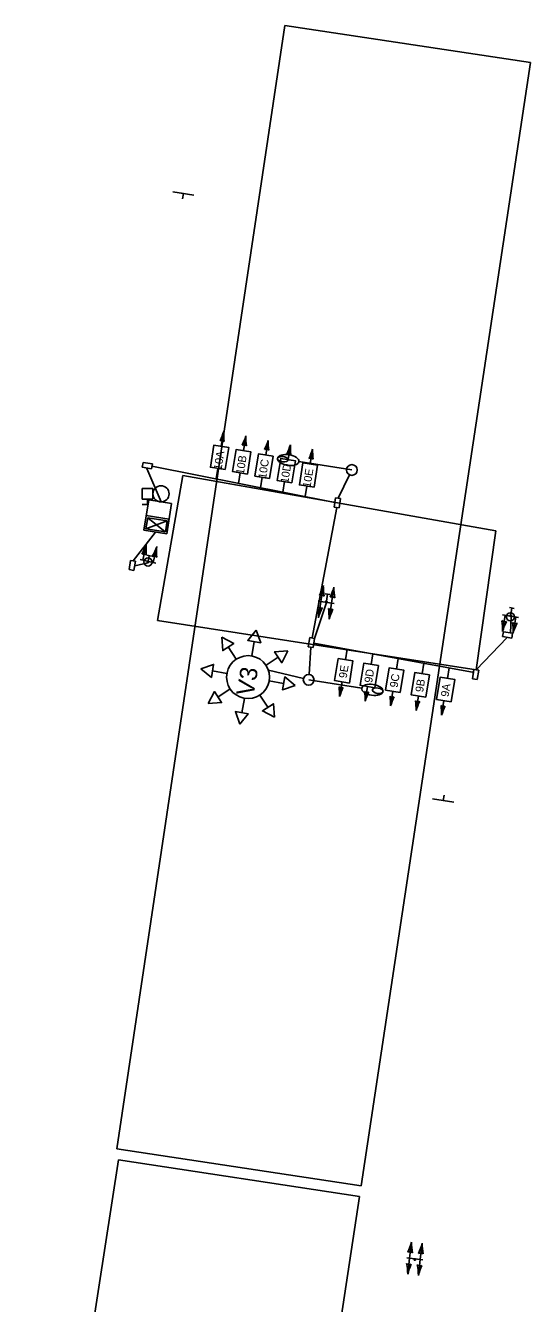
# Model space of a CAD drawing. Extents: x 991933 to 997296, y 1973751 to 1976728.
# Drawn here: x 992033.2 to 992127.2, y 1975751.3 to 1975989 of the extents above; entities that cross this region are included whole.
import ezdxf

# ---------------------------------------------------------------- set-up
doc = ezdxf.new("R2010")
doc.units = 0
for name, color, linetype in [('S_CROSS_DRAIN', 7, 'Continuous'), ('S_CURB', 7, 'Continuous'), ('S_DRIVEWAY', 7, 'Continuous'), ('S_PARKING', 7, 'Continuous'), ('S_PAVEMENT_CROWN', 7, 'Continuous'), ('S_SIDEWALK', 7, 'Continuous'), ('S_WALL', 7, 'Continuous')]:
    doc.layers.add(name, color=color, linetype=linetype)

msp = doc.modelspace()

# ---------------------------------------------------------------- linework, layer by layer
at = {"layer": 'S_CROSS_DRAIN'}
for p, q in [((992060.59, 1975958.11), (992062.57, 1975957.81)), ((992060.59, 1975958.11), (992064.55, 1975957.5)), ((992062.57, 1975957.81), (992062.42, 1975956.82)), ((992108.98, 1975845.2), (992110.95, 1975844.9)), ((992108.98, 1975845.2), (992112.93, 1975844.59)), ((992110.95, 1975844.9), (992111.11, 1975845.88))]:
    msp.add_line(p, q, dxfattribs=at)
at = {"layer": 'S_CURB'}
for p, q in [((992055.02, 1975889.59), (992055.66, 1975892.54)), ((992056.97, 1975889.16), (992057.62, 1975892.12)), ((992057.46, 1975889.06), (992054.53, 1975889.7)), ((992055.82, 1975889.16), (992055.87, 1975889.4)), ((992055.82, 1975889.16), (992056.07, 1975889.11)), ((992056.12, 1975889.35), (992055.87, 1975889.4)), ((992056.12, 1975889.35), (992056.07, 1975889.11)), ((992088.19, 1975881.89), (992088.64, 1975884.88)), ((992090.17, 1975881.59), (992090.62, 1975884.58)), ((992087.69, 1975881.96), (992090.66, 1975881.52)), ((992088.19, 1975881.89), (992087.74, 1975878.9)), ((992089.05, 1975881.76), (992089.09, 1975882.01)), ((992089.05, 1975881.76), (992089.3, 1975881.72)), ((992089.34, 1975881.97), (992089.09, 1975882.01)), ((992089.34, 1975881.97), (992089.3, 1975881.72)), ((992090.17, 1975881.59), (992089.72, 1975878.61)), ((992122.5, 1975879.34), (992121.99, 1975876.36)), ((992122, 1975879.42), (992124.96, 1975878.92)), ((992123.36, 1975879.19), (992123.4, 1975879.44)), ((992123.36, 1975879.19), (992123.61, 1975879.15)), ((992123.65, 1975879.4), (992123.4, 1975879.44)), ((992123.65, 1975879.4), (992123.61, 1975879.15)), ((992124.47, 1975879), (992123.97, 1975876.03)), ((992104.69, 1975759.76), (992105.04, 1975762.76)), ((992106.68, 1975759.53), (992107.02, 1975762.53)), ((992107.17, 1975759.47), (992104.19, 1975759.82)), ((992104.69, 1975759.76), (992104.35, 1975756.76)), ((992105.53, 1975759.41), (992105.56, 1975759.66)), ((992105.53, 1975759.41), (992105.78, 1975759.38)), ((992105.81, 1975759.63), (992105.56, 1975759.66)), ((992105.81, 1975759.63), (992105.78, 1975759.38)), ((992106.68, 1975759.53), (992106.33, 1975756.53))]:
    msp.add_line(p, q, dxfattribs=at)
for centre, radius in [((992093.95, 1975906.38), 1), ((992055.99, 1975889.26), 0.75), ((992123.47, 1975879.06), 0.75), ((992085.91, 1975867.34), 1)]:
    msp.add_circle(centre, radius, dxfattribs=at)
for centre, radius, start, end in [((992041.9, 1975897.8), 14.74, 331.3534, 339.0915), ((992070.37, 1975891.59), 14.74, 176.3082, 184.0463), ((992043.85, 1975897.37), 14.74, 331.3534, 339.0915), ((992072.32, 1975891.17), 14.74, 176.3082, 184.0463), ((992055.1, 1975889.97), 0.814, 45.8525, 109.5472), ((992057.06, 1975889.54), 0.814, 45.8525, 109.5472), ((992074.56, 1975889.22), 14.74, 335.1226, 342.8607), ((992103.37, 1975884.9), 14.74, 180.0773, 187.8155), ((992088.25, 1975882.27), 0.814, 49.6217, 113.3163), ((992076.53, 1975888.92), 14.74, 335.1226, 342.8607), ((992090.22, 1975881.98), 0.814, 49.6217, 113.3163), ((992105.35, 1975884.6), 14.74, 180.0773, 187.8155), ((992088.13, 1975881.51), 0.814, 229.6217, 293.3164), ((992073, 1975878.88), 14.74, 0.0773, 7.8155), ((992101.82, 1975874.56), 14.74, 155.1226, 162.8607), ((992090.11, 1975881.21), 0.814, 229.6217, 293.3164), ((992074.98, 1975878.59), 14.74, 0.0773, 7.8155), ((992103.8, 1975874.26), 14.74, 155.1226, 162.8607), ((992122.43, 1975878.96), 0.814, 228.5683, 292.2629), ((992107.26, 1975876.61), 14.74, 359.0239, 6.762), ((992135.99, 1975871.76), 14.74, 154.0692, 161.8073), ((992124.4, 1975878.62), 0.814, 228.5683, 292.2629), ((992109.23, 1975876.28), 14.74, 359.0239, 6.762), ((992137.97, 1975871.42), 14.74, 154.0692, 161.8073), ((992090.82, 1975766.62), 14.74, 337.0766, 344.8147), ((992119.76, 1975763.28), 14.74, 182.0313, 189.7695), ((992092.8, 1975766.39), 14.74, 337.0766, 344.8147), ((992121.75, 1975763.05), 14.74, 182.0313, 189.7695), ((992104.74, 1975760.14), 0.814, 51.5757, 115.2703), ((992106.72, 1975759.91), 0.814, 51.5757, 115.2703), ((992104.65, 1975759.37), 0.814, 231.5757, 295.2703), ((992089.62, 1975756.24), 14.74, 2.0313, 9.7695), ((992118.57, 1975752.9), 14.74, 157.0766, 164.8147), ((992106.63, 1975759.15), 0.814, 231.5757, 295.2703), ((992091.61, 1975756.01), 14.74, 2.0313, 9.7695), ((992120.55, 1975752.67), 14.74, 157.0766, 164.8147)]:
    msp.add_arc(centre, radius, start, end, dxfattribs=at)
at = {"layer": 'S_DRIVEWAY'}
for p, q in [((992055.07, 1975907.8), (992054.93, 1975906.9)), ((992054.93, 1975906.9), (992056.65, 1975906.62)), ((992056.8, 1975907.53), (992055.07, 1975907.8)), ((992056.65, 1975906.62), (992056.8, 1975907.53)), ((992090.92, 1975901.18), (992090.68, 1975899.45)), ((992090.68, 1975899.45), (992091.59, 1975899.32)), ((992091.83, 1975901.05), (992090.92, 1975901.18)), ((992091.59, 1975899.32), (992091.83, 1975901.05)), ((992052.74, 1975889.56), (992052.47, 1975887.84)), ((992053.65, 1975889.42), (992052.74, 1975889.56)), ((992056.65, 1975890.33), (992055.8, 1975890.51)), ((992055.94, 1975889.13), (992056.22, 1975890.42)), ((992052.47, 1975887.84), (992053.38, 1975887.69)), ((992053.38, 1975887.69), (992053.65, 1975889.42)), ((992089.84, 1975883.23), (992088.98, 1975883.36)), ((992089.22, 1975881.99), (992089.41, 1975883.29)), ((992124.17, 1975880.64), (992123.31, 1975880.79)), ((992123.53, 1975879.42), (992123.74, 1975880.72)), ((992122.15, 1975876.29), (992122, 1975875.38)), ((992122, 1975875.38), (992123.73, 1975875.11)), ((992123.88, 1975876.02), (992122.15, 1975876.29)), ((992123.73, 1975875.11), (992123.88, 1975876.02)), ((992086.1, 1975875.2), (992085.83, 1975873.47)), ((992085.83, 1975873.47), (992086.74, 1975873.33)), ((992087.01, 1975875.05), (992086.1, 1975875.2)), ((992086.74, 1975873.33), (992087.01, 1975875.05)), ((992116.65, 1975869.26), (992116.38, 1975867.54)), ((992117.56, 1975869.12), (992116.65, 1975869.26)), ((992117.29, 1975867.39), (992117.56, 1975869.12)), ((992116.38, 1975867.54), (992117.29, 1975867.39))]:
    msp.add_line(p, q, dxfattribs=at)
at = {"layer": 'S_PARKING'}
for p, q in [((992058.41, 1975900.44), (992055.78, 1975906.67)), ((992056.73, 1975907.08), (992090.8, 1975900.32)), ((992093.51, 1975905.48), (992091.38, 1975901.12)), ((992054.91, 1975902.94), (992054.91, 1975900.94)), ((992054.91, 1975902.94), (992056.91, 1975902.94)), ((992056.91, 1975902.94), (992056.91, 1975900.94)), ((992054.91, 1975900.94), (992056.91, 1975900.94)), ((992054.91, 1975899.94), (992055.91, 1975899.94)), ((992055.91, 1975900.94), (992055.91, 1975899.94)), ((992091.13, 1975899.39), (992086.56, 1975875.13)), ((992057.36, 1975894.83), (992053.2, 1975889.49)), ((992053.51, 1975888.56), (992055.94, 1975889.13)), ((992089.2, 1975881.7), (992087.01, 1975875.05)), ((992123.61, 1975879.15), (992123.46, 1975876.04)), ((992122.87, 1975875.24), (992117.11, 1975869.19)), ((992086.28, 1975873.4), (992085.97, 1975868.34)), ((992086.87, 1975874.19), (992116.69, 1975868.72))]:
    msp.add_line(p, q, dxfattribs=at)
msp.add_circle((992058.41, 1975901.94), 1.5, dxfattribs=at)
at = {"layer": 'S_PAVEMENT_CROWN'}
for p, q in [((992056.12, 1975900.84), (992055.23, 1975895.17)), ((992060.39, 1975900.17), (992056.12, 1975900.84)), ((992060.39, 1975900.17), (992059.5, 1975894.5)), ((992055.93, 1975897.5), (992055.6, 1975895.44)), ((992055.6, 1975895.44), (992059.55, 1975896.93)), ((992059.93, 1975897.2), (992055.65, 1975897.88)), ((992059.55, 1975896.93), (992055.93, 1975897.5)), ((992059.21, 1975894.88), (992055.93, 1975897.5)), ((992059.55, 1975896.93), (992059.23, 1975894.88)), ((992059.5, 1975894.5), (992055.23, 1975895.17)), ((992059.23, 1975894.88), (992055.6, 1975895.44))]:
    msp.add_line(p, q, dxfattribs=at)
at = {"layer": 'S_SIDEWALK'}
for p, q in [((992069.64, 1975910.79), (992070.08, 1975913.52)), ((992073.78, 1975909.97), (992074.22, 1975912.7)), ((992077.92, 1975909.15), (992078.36, 1975911.88)), ((992082.06, 1975908.32), (992082.49, 1975911.06)), ((992086.19, 1975907.5), (992086.63, 1975910.23)), ((992068.67, 1975904.71), (992068.99, 1975906.67)), ((992093.95, 1975906.38), (992084.07, 1975907.93)), ((992072.81, 1975903.89), (992073.13, 1975905.85)), ((992076.95, 1975903.07), (992077.27, 1975905.03)), ((992081.09, 1975902.24), (992081.4, 1975904.21)), ((992085.23, 1975901.42), (992085.54, 1975903.39)), ((992072.42, 1975871.18), (992070.92, 1975873.45)), ((992075.31, 1975871.78), (992075.77, 1975874.46)), ((992093.09, 1975873.05), (992092.78, 1975871.08)), ((992077.96, 1975870.04), (992080.23, 1975871.54)), ((992097.84, 1975872.18), (992097.52, 1975870.21)), ((992102.58, 1975871.31), (992102.26, 1975869.34)), ((992070.68, 1975868.53), (992068, 1975869)), ((992084.94, 1975867.57), (992078.41, 1975869.12)), ((992107.33, 1975870.44), (992107.01, 1975868.47)), ((992112.07, 1975869.57), (992111.75, 1975867.6)), ((992078.56, 1975867.15), (992081.24, 1975866.69)), ((992085.91, 1975867.34), (992095.79, 1975865.79)), ((992092.11, 1975866.97), (992091.67, 1975864.24)), ((992096.86, 1975866.1), (992096.42, 1975863.37)), ((992071.28, 1975865.64), (992069.01, 1975864.14)), ((992073.93, 1975863.9), (992073.46, 1975861.22)), ((992076.82, 1975864.5), (992078.32, 1975862.23)), ((992101.6, 1975865.23), (992101.16, 1975862.5)), ((992106.34, 1975864.36), (992105.91, 1975861.63)), ((992111.09, 1975863.49), (992110.65, 1975860.76))]:
    msp.add_line(p, q, dxfattribs=at)
for points in [[(992070.35, 1975906.45), (992067.61, 1975906.89), (992068.27, 1975911.01), (992071.01, 1975910.57)], [(992074.49, 1975905.63), (992071.75, 1975906.07), (992072.41, 1975910.19), (992075.15, 1975909.75)], [(992078.63, 1975904.81), (992075.89, 1975905.25), (992076.55, 1975909.37), (992079.29, 1975908.92)], [(992082.77, 1975903.99), (992080.03, 1975904.43), (992080.69, 1975908.54), (992083.43, 1975908.1)], [(992086.91, 1975903.17), (992084.17, 1975903.61), (992084.83, 1975907.72), (992087.57, 1975907.28)], [(992069.72, 1975875.27), (992069.9, 1975872.78), (992071.94, 1975874.12)], [(992076.15, 1975876.61), (992074.57, 1975874.67), (992076.97, 1975874.25)], [(992082.05, 1975872.74), (992079.56, 1975872.56), (992080.9, 1975870.52)], [(992093.49, 1975866.75), (992090.74, 1975867.19), (992091.4, 1975871.3), (992094.15, 1975870.86)], [(992065.85, 1975869.37), (992067.79, 1975867.8), (992068.21, 1975870.2)], [(992098.23, 1975865.88), (992095.49, 1975866.32), (992096.15, 1975870.43), (992098.89, 1975869.99)], [(992102.97, 1975865.01), (992100.23, 1975865.45), (992100.89, 1975869.56), (992103.64, 1975869.12)], [(992107.72, 1975864.14), (992104.98, 1975864.58), (992105.64, 1975868.69), (992108.38, 1975868.25)], [(992083.39, 1975866.31), (992081.45, 1975867.89), (992081.03, 1975865.49)], [(992112.46, 1975863.27), (992109.72, 1975863.71), (992110.38, 1975867.82), (992113.12, 1975867.38)], [(992067.19, 1975862.94), (992069.68, 1975863.12), (992068.34, 1975865.16)], [(992073.09, 1975859.07), (992074.66, 1975861.01), (992072.26, 1975861.43)], [(992079.52, 1975860.41), (992079.34, 1975862.9), (992077.3, 1975861.56)]]:
    msp.add_lwpolyline(points, close=True, dxfattribs=at)
msp.add_circle((992074.62, 1975867.84), 4, dxfattribs=at)
for centre, radius, start, end in [((992057.22, 1975917.63), 13.5, 334.5209, 342.2591), ((992083.58, 1975913.4), 13.5, 179.4757, 187.2138), ((992069.69, 1975911.14), 0.746, 49.0201, 112.7147), ((992061.36, 1975916.81), 13.5, 334.5209, 342.2591), ((992073.83, 1975910.32), 0.746, 49.0201, 112.7147), ((992087.71, 1975912.57), 13.5, 179.4757, 187.2138), ((992065.5, 1975915.99), 13.5, 334.5209, 342.2591), ((992091.85, 1975911.75), 13.5, 179.4757, 187.2138), ((992069.64, 1975915.17), 13.5, 334.5209, 342.2591), ((992095.99, 1975910.93), 13.5, 179.4757, 187.2138), ((992077.97, 1975909.5), 0.746, 49.0201, 112.7147), ((992082.11, 1975908.67), 0.746, 49.0201, 112.7147), ((992073.78, 1975914.35), 13.5, 334.5209, 342.2591), ((992086.25, 1975907.85), 0.746, 49.0201, 112.7147), ((992100.13, 1975910.11), 13.5, 179.4757, 187.2138), ((992092.06, 1975866.62), 0.746, 229.02, 292.7147), ((992078.17, 1975864.36), 13.5, 359.4757, 7.2138), ((992104.53, 1975860.13), 13.5, 154.5209, 162.2591), ((992096.8, 1975865.75), 0.746, 229.02, 292.7147), ((992082.92, 1975863.49), 13.5, 359.4757, 7.2138), ((992109.27, 1975859.26), 13.5, 154.5209, 162.2591), ((992101.54, 1975864.88), 0.746, 229.02, 292.7147), ((992087.66, 1975862.62), 13.5, 359.4757, 7.2138), ((992114.02, 1975858.39), 13.5, 154.5209, 162.2591), ((992106.29, 1975864.01), 0.746, 229.02, 292.7147), ((992092.41, 1975861.75), 13.5, 359.4757, 7.2138), ((992118.76, 1975857.52), 13.5, 154.5209, 162.2591), ((992111.03, 1975863.14), 0.746, 229.02, 292.7147), ((992097.15, 1975860.88), 13.5, 359.4757, 7.2138), ((992123.51, 1975856.65), 13.5, 154.5209, 162.2591)]:
    msp.add_arc(centre, radius, start, end, dxfattribs=at)
for centre, major_axis in [((992082.1, 1975908.23), (-1.98, 0.31)), ((992081.11, 1975908.39), (0.988, -0.155)), ((992097.77, 1975865.48), (1.98, -0.31)), ((992098.76, 1975865.32), (-0.988, 0.155))]:
    msp.add_ellipse(centre, major_axis=major_axis, ratio=0.5, dxfattribs=at)
at = {"layer": 'S_WALL'}
for p, q in [((992050.19, 1975780.1), (992081.47, 1975989.05)), ((992081.47, 1975989.05), (992127.2, 1975982.2)), ((992127.2, 1975982.2), (992095.66, 1975773.24)), ((992057.76, 1975878.35), (992062.45, 1975905.35)), ((992062.45, 1975905.35), (992120.74, 1975895.07)), ((992120.74, 1975895.07), (992117.11, 1975869.19)), ((992117.11, 1975869.19), (992057.76, 1975878.35)), ((992033.19, 1975665.65), (992050.48, 1975778.04)), ((992095.66, 1975773.24), (992050.19, 1975780.1)), ((992050.48, 1975778.04), (992095.36, 1975771.26))]:
    msp.add_line(p, q, dxfattribs=at)
msp.add_lwpolyline([(992095.36, 1975771.26), (992087.02, 1975715.99), (992084.81, 1975701.23), (992082.59, 1975686.4), (992080.35, 1975671.48), (992078.47, 1975658.68)], dxfattribs=at)

# ---------------------------------------------------------------- texts
at = {"layer": 'S_SIDEWALK'}
for s, height, rotation, p in [('10A', 1.489, 81.068, (992069.68, 1975906.29)), ('10B', 1.489, 81.068, (992073.82, 1975905.47)), ('10C', 1.489, 81.068, (992077.96, 1975904.65)), ('10D', 1.489, 81.068, (992082.1, 1975903.83)), ('10E', 1.489, 81.068, (992086.24, 1975903)), ('V3', 3.25, 80.1027, (992075.6, 1975864.17)), ('9E', 1.489, 81.3279, (992092.98, 1975867.57)), ('9D', 1.489, 81.3279, (992097.72, 1975866.71)), ('9C', 1.489, 81.3279, (992102.46, 1975865.83)), ('9B', 1.489, 81.3279, (992107.21, 1975864.96)), ('9A', 1.489, 81.3279, (992111.95, 1975864.1))]:
    msp.add_text(s, height=height, rotation=rotation, dxfattribs=at).set_placement(p)

doc.saveas('drawing.dxf')
